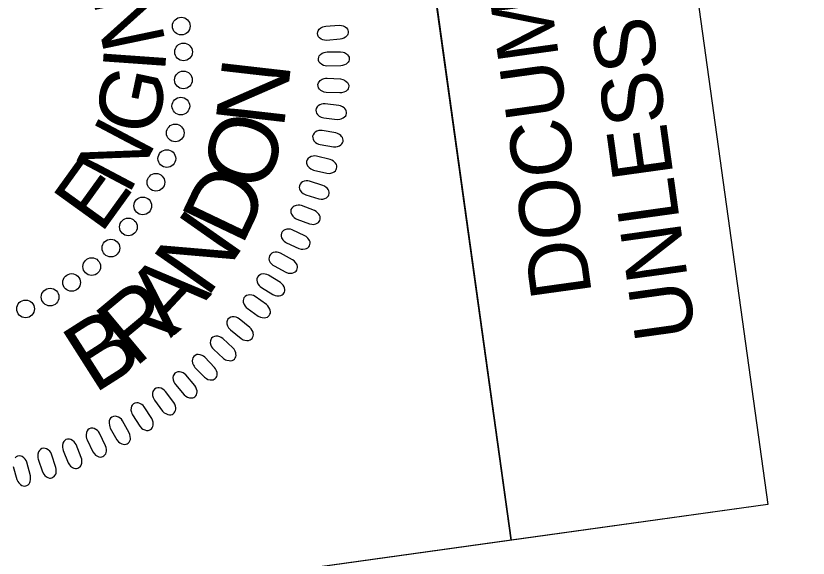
# Model space of a CAD drawing. Extents: x 477151 to 478666, y 496366 to 498184.
# Drawn here: x 477505.6 to 477577.4, y 497840.5 to 497889.6 of the extents above; entities that cross this region are included whole.
import ezdxf

# ---------------------------------------------------------------- set-up
doc = ezdxf.new("R2010")
doc.units = 0
for name, color, linetype in [('Sheet Clip Boundary CELL', 7, 'Continuous'), ('Sheet PE Seal Cell', 7, 'Continuous'), ('Sheet Plan CELL', 7, 'Continuous'), ('Sheet Sticker Exception Certification CELL', 7, 'Continuous')]:
    doc.layers.add(name, color=color, linetype=linetype)

msp = doc.modelspace()

# ---------------------------------------------------------------- linework, layer by layer
at = {"layer": 'Sheet Clip Boundary CELL'}
msp.add_lwpolyline([(477521.555, 496961.065), (477576.758, 496564.392), (477581.003, 496533.885), (477980.846, 496589.529), (477967.104, 496688.277), (477990.561, 496691.362), (478608.234, 496770.21), (478458.668, 497790.409), (478383.404, 497784.943), (478355.708, 497983.959), (478358.482, 497984.345), (478349.141, 498051.468), (477730.123, 497965.317), (477560.309, 497941.691), (477573.713, 497845.373), (477401.821, 497821.439)], close=True, dxfattribs=at)
at = {"layer": 'Sheet PE Seal Cell'}
for points in [[(477533.638, 497888.675), (477534.862, 497888.767), (477535.083, 497888.746), (477535.227, 497888.705), (477535.404, 497888.605), (477535.522, 497888.517), (477535.609, 497888.411), (477535.657, 497888.31), (477535.685, 497888.199), (477535.673, 497888.086), (477535.652, 497887.965), (477535.601, 497887.856), (477535.509, 497887.744), (477535.434, 497887.678), (477535.29, 497887.6), (477535.115, 497887.527), (477534.958, 497887.492), (477533.705, 497887.39), (477533.535, 497887.4), (477533.392, 497887.435), (477533.226, 497887.512), (477533.078, 497887.613), (477532.992, 497887.705), (477532.92, 497887.856), (477532.889, 497888.004), (477532.918, 497888.156), (477532.96, 497888.264), (477533.049, 497888.398), (477533.21, 497888.53), (477533.384, 497888.611), (477533.51, 497888.65)], [(477533.762, 497886.353), (477534.989, 497886.367), (477535.209, 497886.333), (477535.349, 497886.282), (477535.521, 497886.172), (477535.631, 497886.076), (477535.713, 497885.965), (477535.753, 497885.861), (477535.774, 497885.749), (477535.756, 497885.637), (477535.728, 497885.517), (477535.67, 497885.412), (477535.57, 497885.306), (477535.491, 497885.245), (477535.342, 497885.176), (477535.164, 497885.114), (477535.005, 497885.09), (477533.749, 497885.066), (477533.579, 497885.087), (477533.438, 497885.131), (477533.278, 497885.218), (477533.137, 497885.328), (477533.056, 497885.425), (477532.994, 497885.581), (477532.973, 497885.73), (477533.011, 497885.88), (477533.059, 497885.985), (477533.157, 497886.114), (477533.325, 497886.234), (477533.504, 497886.305), (477533.633, 497886.336)], [(477533.765, 497883.964), (477534.991, 497883.902), (477535.208, 497883.854), (477535.345, 497883.795), (477535.509, 497883.674), (477535.613, 497883.571), (477535.687, 497883.455), (477535.722, 497883.349), (477535.736, 497883.236), (477535.71, 497883.125), (477535.674, 497883.007), (477535.609, 497882.906), (477535.505, 497882.806), (477535.422, 497882.75), (477535.269, 497882.691), (477535.086, 497882.64), (477534.926, 497882.626), (477533.671, 497882.682), (477533.502, 497882.713), (477533.366, 497882.765), (477533.211, 497882.862), (477533.077, 497882.981), (477533.002, 497883.082), (477532.95, 497883.242), (477532.938, 497883.393), (477532.986, 497883.539), (477533.041, 497883.642), (477533.146, 497883.764), (477533.322, 497883.874), (477533.505, 497883.933), (477533.635, 497883.955)], [(477533.471, 497880.367), (477534.69, 497880.228), (477534.911, 497880.241), (477535.056, 497880.276), (477535.238, 497880.369), (477535.358, 497880.453), (477535.45, 497880.556), (477535.501, 497880.655), (477535.534, 497880.764), (477535.526, 497880.877), (477535.51, 497881), (477535.463, 497881.111), (477535.375, 497881.226), (477535.304, 497881.295), (477535.162, 497881.378), (477534.99, 497881.458), (477534.834, 497881.498), (477533.587, 497881.648), (477533.416, 497881.645), (477533.272, 497881.616), (477533.103, 497881.545), (477532.952, 497881.449), (477532.862, 497881.362), (477532.784, 497881.212), (477532.748, 497881.066), (477532.77, 497880.913), (477532.808, 497880.803), (477532.893, 497880.666), (477533.048, 497880.528), (477533.219, 497880.44), (477533.344, 497880.397)], [(477533.126, 497877.964), (477534.334, 497877.749), (477534.556, 497877.747), (477534.703, 497877.774), (477534.89, 497877.855), (477535.015, 497877.931), (477535.113, 497878.028), (477535.17, 497878.123), (477535.21, 497878.231), (477535.209, 497878.344), (477535.201, 497878.468), (477535.161, 497878.581), (477535.08, 497878.701), (477535.012, 497878.774), (477534.877, 497878.867), (477534.711, 497878.957), (477534.558, 497879.007), (477533.322, 497879.235), (477533.151, 497879.242), (477533.006, 497879.222), (477532.833, 497879.162), (477532.676, 497879.077), (477532.58, 497878.994), (477532.494, 497878.851), (477532.448, 497878.707), (477532.461, 497878.553), (477532.492, 497878.441), (477532.567, 497878.298), (477532.713, 497878.152), (477532.879, 497878.053), (477533.001, 497878.001)], [(477532.537, 497875.652), (477533.729, 497875.361), (477533.951, 497875.346), (477534.099, 497875.363), (477534.29, 497875.432), (477534.42, 497875.5), (477534.524, 497875.591), (477534.587, 497875.683), (477534.633, 497875.788), (477534.64, 497875.9), (477534.639, 497876.024), (477534.607, 497876.14), (477534.534, 497876.265), (477534.471, 497876.342), (477534.341, 497876.443), (477534.181, 497876.544), (477534.032, 497876.604), (477532.812, 497876.908), (477532.642, 497876.927), (477532.496, 497876.915), (477532.32, 497876.866), (477532.158, 497876.791), (477532.057, 497876.715), (477531.961, 497876.577), (477531.907, 497876.436), (477531.911, 497876.282), (477531.935, 497876.168), (477532.001, 497876.021), (477532.137, 497875.865), (477532.296, 497875.757), (477532.415, 497875.697)], [(477531.832, 497873.406), (477533.003, 497873.041), (477533.223, 497873.012), (477533.372, 497873.02), (477533.568, 497873.076), (477533.701, 497873.137), (477533.81, 497873.22), (477533.88, 497873.308), (477533.932, 497873.41), (477533.946, 497873.522), (477533.953, 497873.645), (477533.927, 497873.763), (477533.863, 497873.893), (477533.805, 497873.974), (477533.682, 497874.082), (477533.529, 497874.193), (477533.383, 497874.262), (477532.185, 497874.642), (477532.016, 497874.671), (477531.87, 497874.669), (477531.691, 497874.632), (477531.524, 497874.567), (477531.419, 497874.497), (477531.316, 497874.365), (477531.252, 497874.228), (477531.245, 497874.074), (477531.262, 497873.958), (477531.319, 497873.808), (477531.445, 497873.644), (477531.598, 497873.526), (477531.712, 497873.459)], [(477531.019, 497871.213), (477532.165, 497870.776), (477532.384, 497870.733), (477532.533, 497870.731), (477532.731, 497870.776), (477532.869, 497870.827), (477532.983, 497870.904), (477533.058, 497870.987), (477533.116, 497871.085), (477533.137, 497871.196), (477533.152, 497871.319), (477533.134, 497871.438), (477533.078, 497871.572), (477533.025, 497871.656), (477532.909, 497871.772), (477532.762, 497871.892), (477532.622, 497871.97), (477531.45, 497872.425), (477531.284, 497872.464), (477531.137, 497872.472), (477530.956, 497872.445), (477530.786, 497872.391), (477530.677, 497872.328), (477530.565, 497872.203), (477530.493, 497872.07), (477530.477, 497871.917), (477530.486, 497871.801), (477530.534, 497871.647), (477530.65, 497871.475), (477530.793, 497871.347), (477530.903, 497871.273)], [(477530.093, 497869.047), (477531.21, 497868.539), (477531.425, 497868.481), (477531.574, 497868.471), (477531.775, 497868.503), (477531.915, 497868.546), (477532.034, 497868.615), (477532.114, 497868.693), (477532.178, 497868.788), (477532.207, 497868.897), (477532.229, 497869.019), (477532.218, 497869.139), (477532.171, 497869.275), (477532.123, 497869.363), (477532.015, 497869.486), (477531.876, 497869.615), (477531.74, 497869.702), (477530.6, 497870.229), (477530.436, 497870.279), (477530.291, 497870.296), (477530.108, 497870.281), (477529.935, 497870.237), (477529.822, 497870.181), (477529.702, 497870.064), (477529.622, 497869.935), (477529.597, 497869.783), (477529.598, 497869.667), (477529.636, 497869.51), (477529.741, 497869.331), (477529.877, 497869.195), (477529.982, 497869.114)], [(477528.956, 497866.969), (477530.039, 497866.391), (477530.249, 497866.321), (477530.397, 497866.301), (477530.6, 497866.32), (477530.743, 497866.355), (477530.866, 497866.416), (477530.95, 497866.489), (477531.021, 497866.579), (477531.056, 497866.687), (477531.085, 497866.807), (477531.082, 497866.927), (477531.043, 497867.067), (477531.002, 497867.157), (477530.901, 497867.286), (477530.771, 497867.424), (477530.641, 497867.519), (477529.536, 497868.117), (477529.376, 497868.177), (477529.231, 497868.203), (477529.048, 497868.199), (477528.872, 497868.167), (477528.756, 497868.118), (477528.629, 497868.008), (477528.541, 497867.885), (477528.506, 497867.734), (477528.501, 497867.619), (477528.528, 497867.46), (477528.622, 497867.275), (477528.749, 497867.13), (477528.849, 497867.043)], [(477527.814, 497865.012), (477528.858, 497864.367), (477529.065, 497864.284), (477529.211, 497864.255), (477529.414, 497864.261), (477529.559, 497864.287), (477529.685, 497864.34), (477529.775, 497864.408), (477529.851, 497864.493), (477529.892, 497864.598), (477529.929, 497864.716), (477529.933, 497864.836), (477529.903, 497864.978), (477529.867, 497865.071), (477529.775, 497865.207), (477529.654, 497865.352), (477529.53, 497865.455), (477528.465, 497866.121), (477528.309, 497866.191), (477528.166, 497866.226), (477527.983, 497866.234), (477527.806, 497866.212), (477527.686, 497866.171), (477527.553, 497866.069), (477527.458, 497865.952), (477527.413, 497865.804), (477527.401, 497865.688), (477527.419, 497865.528), (477527.5, 497865.338), (477527.618, 497865.185), (477527.712, 497865.092)], [(477526.532, 497863.127), (477527.533, 497862.418), (477527.734, 497862.322), (477527.878, 497862.284), (477528.081, 497862.277), (477528.228, 497862.293), (477528.357, 497862.339), (477528.449, 497862.401), (477528.531, 497862.481), (477528.579, 497862.584), (477528.624, 497862.7), (477528.636, 497862.819), (477528.614, 497862.962), (477528.584, 497863.057), (477528.501, 497863.199), (477528.389, 497863.351), (477528.272, 497863.462), (477527.25, 497864.194), (477527.099, 497864.273), (477526.959, 497864.317), (477526.777, 497864.336), (477526.599, 497864.325), (477526.477, 497864.292), (477526.337, 497864.199), (477526.234, 497864.088), (477526.181, 497863.943), (477526.162, 497863.829), (477526.169, 497863.668), (477526.239, 497863.472), (477526.346, 497863.313), (477526.435, 497863.214)], [(477525.01, 497861.163), (477525.965, 497860.393), (477526.158, 497860.284), (477526.3, 497860.237), (477526.503, 497860.218), (477526.649, 497860.225), (477526.781, 497860.262), (477526.878, 497860.318), (477526.964, 497860.393), (477527.019, 497860.493), (477527.071, 497860.605), (477527.09, 497860.723), (477527.078, 497860.868), (477527.053, 497860.964), (477526.979, 497861.111), (477526.877, 497861.27), (477526.767, 497861.388), (477525.794, 497862.182), (477525.648, 497862.272), (477525.511, 497862.324), (477525.331, 497862.355), (477525.151, 497862.355), (477525.029, 497862.329), (477524.883, 497862.245), (477524.774, 497862.141), (477524.711, 497862), (477524.684, 497861.887), (477524.682, 497861.725), (477524.739, 497861.526), (477524.836, 497861.36), (477524.918, 497861.256)], [(477523.464, 497859.424), (477524.369, 497858.595), (477524.555, 497858.474), (477524.694, 497858.418), (477524.895, 497858.386), (477525.041, 497858.384), (477525.176, 497858.413), (477525.276, 497858.463), (477525.366, 497858.532), (477525.427, 497858.628), (477525.486, 497858.737), (477525.513, 497858.854), (477525.509, 497858.998), (477525.491, 497859.097), (477525.426, 497859.248), (477525.334, 497859.412), (477525.232, 497859.537), (477524.31, 497860.392), (477524.171, 497860.49), (477524.037, 497860.55), (477523.859, 497860.592), (477523.68, 497860.604), (477523.556, 497860.587), (477523.405, 497860.511), (477523.29, 497860.414), (477523.219, 497860.277), (477523.185, 497860.166), (477523.172, 497860.005), (477523.216, 497859.803), (477523.303, 497859.631), (477523.379, 497859.522)], [(477521.794, 497857.774), (477522.645, 497856.89), (477522.824, 497856.758), (477522.958, 497856.693), (477523.157, 497856.649), (477523.303, 497856.638), (477523.439, 497856.658), (477523.542, 497856.701), (477523.637, 497856.765), (477523.704, 497856.857), (477523.769, 497856.962), (477523.803, 497857.077), (477523.809, 497857.222), (477523.797, 497857.321), (477523.742, 497857.475), (477523.661, 497857.646), (477523.566, 497857.777), (477522.7, 497858.687), (477522.566, 497858.794), (477522.437, 497858.863), (477522.262, 497858.916), (477522.085, 497858.939), (477521.959, 497858.929), (477521.804, 497858.863), (477521.682, 497858.773), (477521.603, 497858.641), (477521.562, 497858.533), (477521.539, 497858.373), (477521.571, 497858.168), (477521.647, 497857.991), (477521.715, 497857.878)], [(477520.014, 497856.238), (477520.808, 497855.302), (477520.978, 497855.158), (477521.108, 497855.086), (477521.304, 497855.029), (477521.448, 497855.008), (477521.586, 497855.02), (477521.691, 497855.057), (477521.79, 497855.115), (477521.862, 497855.203), (477521.934, 497855.303), (477521.975, 497855.416), (477521.99, 497855.56), (477521.984, 497855.659), (477521.939, 497855.817), (477521.868, 497855.992), (477521.783, 497856.128), (477520.975, 497857.092), (477520.849, 497857.207), (477520.723, 497857.284), (477520.552, 497857.348), (477520.376, 497857.382), (477520.25, 497857.38), (477520.092, 497857.324), (477519.965, 497857.242), (477519.877, 497857.115), (477519.83, 497857.01), (477519.797, 497856.851), (477519.816, 497856.645), (477519.881, 497856.463), (477519.942, 497856.346)], [(477518.119, 497854.806), (477518.852, 497853.822), (477519.013, 497853.669), (477519.138, 497853.588), (477519.329, 497853.519), (477519.473, 497853.489), (477519.61, 497853.493), (477519.718, 497853.523), (477519.82, 497853.574), (477519.898, 497853.657), (477519.976, 497853.753), (477520.024, 497853.863), (477520.048, 497854.006), (477520.049, 497854.106), (477520.013, 497854.266), (477519.954, 497854.445), (477519.877, 497854.587), (477519.132, 497855.599), (477519.012, 497855.721), (477518.892, 497855.806), (477518.725, 497855.88), (477518.552, 497855.925), (477518.426, 497855.931), (477518.265, 497855.885), (477518.133, 497855.812), (477518.037, 497855.691), (477517.983, 497855.588), (477517.94, 497855.432), (477517.946, 497855.225), (477517.999, 497855.04), (477518.053, 497854.919)], [(477516.134, 497853.473), (477516.805, 497852.445), (477516.956, 497852.282), (477517.076, 497852.193), (477517.263, 497852.113), (477517.404, 497852.074), (477517.542, 497852.068), (477517.651, 497852.092), (477517.756, 497852.136), (477517.838, 497852.214), (477517.922, 497852.305), (477517.977, 497852.412), (477518.01, 497852.553), (477518.017, 497852.652), (477517.992, 497852.814), (477517.943, 497852.997), (477517.875, 497853.143), (477517.196, 497854.2), (477517.084, 497854.33), (477516.97, 497854.422), (477516.808, 497854.507), (477516.638, 497854.563), (477516.513, 497854.577), (477516.348, 497854.541), (477516.212, 497854.476), (477516.109, 497854.361), (477516.048, 497854.261), (477515.996, 497854.109), (477515.99, 497853.902), (477516.031, 497853.714), (477516.076, 497853.59)], [(477514.12, 497852.284), (477514.724, 497851.216), (477514.865, 497851.044), (477514.979, 497850.947), (477515.16, 497850.855), (477515.299, 497850.808), (477515.436, 497850.794), (477515.546, 497850.81), (477515.654, 497850.848), (477515.741, 497850.921), (477515.831, 497851.006), (477515.892, 497851.109), (477515.934, 497851.248), (477515.947, 497851.346), (477515.932, 497851.51), (477515.895, 497851.695), (477515.836, 497851.846), (477515.224, 497852.943), (477515.121, 497853.08), (477515.013, 497853.179), (477514.857, 497853.273), (477514.69, 497853.34), (477514.566, 497853.362), (477514.4, 497853.336), (477514.26, 497853.28), (477514.15, 497853.172), (477514.083, 497853.076), (477514.022, 497852.927), (477514.002, 497852.721), (477514.031, 497852.531), (477514.069, 497852.404)], [(477512.009, 497851.224), (477512.545, 497850.121), (477512.674, 497849.94), (477512.781, 497849.837), (477512.957, 497849.733), (477513.093, 497849.677), (477513.228, 497849.654), (477513.339, 497849.664), (477513.449, 497849.695), (477513.541, 497849.762), (477513.636, 497849.842), (477513.704, 497849.941), (477513.754, 497850.076), (477513.774, 497850.174), (477513.768, 497850.338), (477513.744, 497850.526), (477513.694, 497850.679), (477513.152, 497851.813), (477513.057, 497851.955), (477512.956, 497852.061), (477512.806, 497852.165), (477512.644, 497852.242), (477512.522, 497852.272), (477512.355, 497852.257), (477512.211, 497852.209), (477512.094, 497852.108), (477512.022, 497852.018), (477511.951, 497851.873), (477511.918, 497851.668), (477511.935, 497851.477), (477511.966, 497851.347)], [(477509.837, 497850.262), (477510.302, 497849.127), (477510.42, 497848.938), (477510.521, 497848.828), (477510.689, 497848.714), (477510.821, 497848.65), (477510.955, 497848.619), (477511.067, 497848.622), (477511.179, 497848.646), (477511.274, 497848.706), (477511.373, 497848.779), (477511.448, 497848.874), (477511.507, 497849.007), (477511.532, 497849.103), (477511.538, 497849.267), (477511.524, 497849.456), (477511.485, 497849.612), (477511.015, 497850.777), (477510.93, 497850.926), (477510.835, 497851.038), (477510.692, 497851.151), (477510.535, 497851.238), (477510.415, 497851.275), (477510.247, 497851.271), (477510.101, 497851.232), (477509.978, 497851.139), (477509.9, 497851.053), (477509.82, 497850.913), (477509.774, 497850.71), (477509.779, 497850.518), (477509.802, 497850.387)], [(477507.584, 497849.464), (477507.977, 497848.302), (477508.083, 497848.106), (477508.177, 497847.991), (477508.338, 497847.866), (477508.465, 497847.793), (477508.597, 497847.754), (477508.709, 497847.75), (477508.822, 497847.767), (477508.921, 497847.822), (477509.025, 497847.888), (477509.105, 497847.978), (477509.172, 497848.107), (477509.203, 497848.201), (477509.219, 497848.365), (477509.218, 497848.554), (477509.188, 497848.712), (477508.792, 497849.905), (477508.716, 497850.058), (477508.629, 497850.176), (477508.493, 497850.298), (477508.342, 497850.395), (477508.224, 497850.439), (477508.057, 497850.445), (477507.908, 497850.416), (477507.78, 497850.331), (477507.696, 497850.25), (477507.608, 497850.115), (477507.55, 497849.916), (477507.543, 497849.723), (477507.557, 497849.592)]]:
    msp.add_lwpolyline(points, close=True, dxfattribs=at)
msp.add_lwpolyline([(477505.327, 497848.813), (477505.646, 497847.629), (477505.74, 497847.427), (477505.826, 497847.306), (477505.979, 497847.171), (477506.101, 497847.09), (477506.231, 497847.043), (477506.342, 497847.032), (477506.456, 497847.042), (477506.558, 497847.09), (477506.666, 497847.15), (477506.752, 497847.235), (477506.826, 497847.359), (477506.864, 497847.452), (477506.89, 497847.613), (477506.9, 497847.802), (477506.88, 497847.962), (477506.56, 497849.177), (477506.495, 497849.335), (477506.414, 497849.458), (477506.287, 497849.589), (477506.142, 497849.694), (477506.028, 497849.746), (477505.86, 497849.763), (477505.711, 497849.743), (477505.577, 497849.666), (477505.489, 497849.59)], dxfattribs=at)
for centre in [(477520.552, 497888.686), (477520.757, 497886.343), (477520.746, 497883.81), (477520.511, 497881.446), (477520.006, 497879.004), (477519.242, 497876.687), (477518.253, 497874.54), (477517.061, 497872.405), (477515.757, 497870.496), (477514.172, 497868.587), (477512.436, 497866.899), (477510.612, 497865.465), (477508.663, 497864.15), (477506.439, 497863.077)]:
    msp.add_circle(centre, 0.801, dxfattribs=at)
at = {"layer": 'Sheet Plan CELL'}
msp.add_lwpolyline([(477439.025, 497826.616), (477425.234, 497925.712), (477536.673, 497941.22), (477550.437, 497842.134)], close=True, dxfattribs=at)
at = {"layer": 'Sheet Sticker Exception Certification CELL'}
for p, q in [((477546.14, 498043.501), (477573.713, 497845.373)), ((477546.14, 498043.501), (477573.713, 497845.373)), ((477550.437, 497842.134), (477522.864, 498040.262)), ((477550.437, 497842.134), (477522.864, 498040.262)), ((477573.713, 497845.373), (477550.437, 497842.134)), ((477573.713, 497845.373), (477550.437, 497842.134))]:
    msp.add_line(p, q, dxfattribs=at)

# ---------------------------------------------------------------- texts
at = {"layer": 'Sheet PE Seal Cell'}
for s, height, rotation, p in [('N', 5.669, 101.82705, (477519.154, 497887.184)), ('I', 5.669, 85.94746, (477519.066, 497884.391)), ('N', 6.236, 83.47319, (477529.838, 497879.311)), ('G', 5.669, 78.00766, (477518.168, 497878.584)), ('N', 5.669, 62.12806, (477515.774, 497873.309)), ('O', 6.236, 73.37334, (477528.254, 497873.485)), ('E', 5.669, 54.18827, (477513.279, 497869.797)), ('D', 6.236, 64.50511, (477526.039, 497868.667)), ('N', 6.236, 55.01542, (477522.877, 497863.957)), ('A', 6.236, 46.90425, (477519.589, 497860.391)), ('R', 6.236, 39.78741, (477516.315, 497857.671)), ('B', 6.236, 32.51238, (477512.645, 497855.332))]:
    msp.add_text(s, height=height, rotation=rotation, dxfattribs=at).set_placement(p)
at = {"layer": 'Sheet Sticker Exception Certification CELL'}
for s, p in [('UNLESS ALL SIGNATURES COMPLETED', (477567.194, 497860.62)), ('UNLESS ALL SIGNATURES COMPLETED', (477567.194, 497860.62)), ('DOCUMENT NOT CONSIDERED FINAL', (477557.779, 497864.43)), ('DOCUMENT NOT CONSIDERED FINAL', (477557.779, 497864.43))]:
    msp.add_text(s, height=5.5, rotation=97.92268, dxfattribs=at).set_placement(p)

doc.saveas('drawing.dxf')
